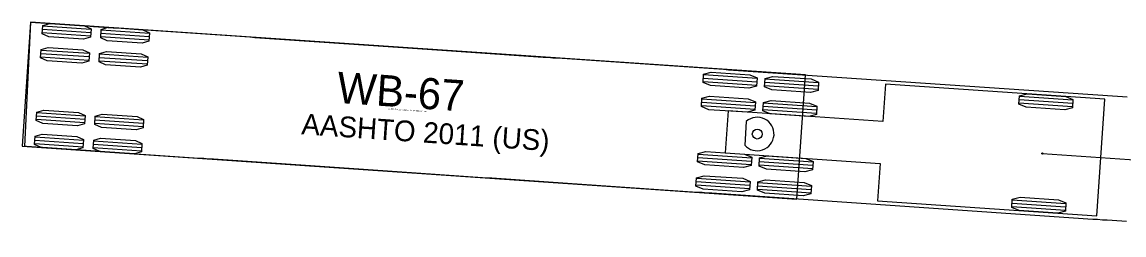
# Model space of a CAD drawing. Extents: x 2175591 to 2194071, y 76570 to 86955.
# Drawn here: x 2192626.4 to 2192701.6, y 86940.2 to 86954.7 of the extents above; entities that cross this region are included whole.
import ezdxf

# ---------------------------------------------------------------- set-up
doc = ezdxf.new("R2010")
doc.units = 0
doc.layers.add('-NOPLT', color=7, linetype='Continuous')

msp = doc.modelspace()

# ---------------------------------------------------------------- linework, layer by layer
at = {"layer": '-NOPLT'}
for p, q in [((2192626.957, 86954.687), (2192626.379, 86946.206)), ((2192679.834, 86951.077), (2192626.957, 86954.687)), ((2192631.067, 86953.947), (2192627.774, 86954.172)), ((2192631.082, 86954.175), (2192627.79, 86954.4)), ((2192635.073, 86953.903), (2192631.781, 86954.128)), ((2192631.051, 86953.718), (2192627.759, 86953.943)), ((2192635.042, 86953.446), (2192631.749, 86953.67)), ((2192635.057, 86953.674), (2192631.765, 86953.899)), ((2192630.97, 86952.529), (2192627.678, 86952.754)), ((2192630.939, 86952.072), (2192627.646, 86952.297)), ((2192630.954, 86952.301), (2192627.662, 86952.525)), ((2192634.929, 86951.8), (2192631.637, 86952.024)), ((2192634.945, 86952.028), (2192631.653, 86952.253)), ((2192634.961, 86952.257), (2192631.668, 86952.482)), ((2192676.543, 86950.822), (2192672.885, 86951.071)), ((2192679.256, 86942.597), (2192679.834, 86951.077)), ((2192679.834, 86951.077), (2192679.834, 86951.077)), ((2192676.511, 86950.364), (2192672.853, 86950.614)), ((2192676.527, 86950.593), (2192672.869, 86950.843)), ((2192680.702, 86950.078), (2192677.044, 86950.328)), ((2192680.717, 86950.307), (2192677.059, 86950.557)), ((2192680.733, 86950.535), (2192677.075, 86950.785)), ((2192685.305, 86950.453), (2192685.13, 86947.892)), ((2192700.27, 86949.432), (2192685.305, 86950.453)), ((2192698.093, 86949.35), (2192694.434, 86949.6)), ((2192676.399, 86948.718), (2192672.741, 86948.968)), ((2192676.415, 86948.947), (2192672.757, 86949.196)), ((2192676.43, 86949.175), (2192672.772, 86949.425)), ((2192680.605, 86948.661), (2192676.947, 86948.91)), ((2192680.621, 86948.889), (2192676.962, 86949.139)), ((2192698.061, 86948.893), (2192694.403, 86949.143)), ((2192698.077, 86949.122), (2192694.419, 86949.372)), ((2192699.725, 86941.45), (2192700.27, 86949.432)), ((2192700.27, 86949.432), (2192700.27, 86949.432)), ((2192630.663, 86948.027), (2192627.37, 86948.252)), ((2192630.678, 86948.256), (2192627.386, 86948.481)), ((2192634.669, 86947.983), (2192631.377, 86948.208)), ((2192674.554, 86948.614), (2192674.359, 86945.754)), ((2192685.13, 86947.892), (2192674.554, 86948.614)), ((2192680.589, 86948.432), (2192676.931, 86948.682)), ((2192630.647, 86947.799), (2192627.355, 86948.023)), ((2192634.638, 86947.526), (2192631.345, 86947.751)), ((2192634.653, 86947.755), (2192631.361, 86947.98)), ((2192675.801, 86947.903), (2192675.691, 86946.29)), ((2192630.55, 86946.381), (2192627.258, 86946.606)), ((2192630.566, 86946.61), (2192627.273, 86946.834)), ((2192634.556, 86946.337), (2192631.264, 86946.562)), ((2192626.379, 86946.206), (2192679.256, 86942.597)), ((2192630.535, 86946.152), (2192627.242, 86946.377)), ((2192634.525, 86945.88), (2192631.233, 86946.105)), ((2192634.541, 86946.109), (2192631.249, 86946.333)), ((2192676.141, 86944.944), (2192672.483, 86945.193)), ((2192676.157, 86945.172), (2192672.499, 86945.422)), ((2192676.173, 86945.401), (2192672.515, 86945.651)), ((2192674.359, 86945.754), (2192684.935, 86945.032)), ((2192680.347, 86944.886), (2192676.689, 86945.136)), ((2192680.363, 86945.115), (2192676.705, 86945.364)), ((2192684.935, 86945.032), (2192684.76, 86942.472)), ((2192696.007, 86945.713), (2192777.484, 86940.151)), ((2192680.332, 86944.658), (2192676.674, 86944.907)), ((2192676.029, 86943.297), (2192672.371, 86943.547)), ((2192676.045, 86943.526), (2192672.387, 86943.776)), ((2192676.06, 86943.755), (2192672.402, 86944.004)), ((2192680.251, 86943.469), (2192676.592, 86943.718)), ((2192680.219, 86943.011), (2192676.561, 86943.261)), ((2192680.235, 86943.24), (2192676.577, 86943.49)), ((2192684.76, 86942.472), (2192699.725, 86941.45)), ((2192697.579, 86941.826), (2192693.921, 86942.076)), ((2192697.595, 86942.055), (2192693.936, 86942.305)), ((2192697.61, 86942.284), (2192693.952, 86942.533))]:
    msp.add_line(p, q, dxfattribs=at)
for points in [[(2192701.753, 86941.061), (2192701.424, 86941.084), (2192701.094, 86941.106), (2192700.765, 86941.129), (2192700.436, 86941.151), (2192700.107, 86941.173), (2192699.778, 86941.196), (2192699.448, 86941.218), (2192699.119, 86941.241), (2192698.79, 86941.263), (2192698.461, 86941.286), (2192698.131, 86941.308), (2192697.802, 86941.331), (2192697.473, 86941.353), (2192697.144, 86941.376), (2192696.815, 86941.398), (2192696.485, 86941.421), (2192696.156, 86941.443), (2192695.827, 86941.466), (2192695.498, 86941.488), (2192695.168, 86941.511), (2192694.839, 86941.533), (2192694.51, 86941.556), (2192694.181, 86941.578), (2192693.852, 86941.6), (2192693.522, 86941.623), (2192693.193, 86941.645), (2192692.864, 86941.668), (2192692.535, 86941.69), (2192692.206, 86941.713), (2192691.876, 86941.735), (2192691.547, 86941.758), (2192691.218, 86941.78), (2192690.889, 86941.803), (2192690.559, 86941.825), (2192690.23, 86941.848), (2192689.901, 86941.87), (2192689.572, 86941.893), (2192689.243, 86941.915), (2192688.913, 86941.938), (2192688.584, 86941.96), (2192688.255, 86941.983), (2192687.926, 86942.005), (2192687.596, 86942.027), (2192687.267, 86942.05), (2192686.938, 86942.072), (2192686.609, 86942.095), (2192686.28, 86942.117), (2192685.95, 86942.14), (2192685.621, 86942.162), (2192685.292, 86942.185), (2192684.963, 86942.207), (2192684.633, 86942.23), (2192684.304, 86942.252), (2192683.975, 86942.275), (2192683.646, 86942.297), (2192683.317, 86942.32), (2192682.987, 86942.342), (2192682.658, 86942.365), (2192682.329, 86942.387), (2192682, 86942.41), (2192681.671, 86942.432), (2192681.341, 86942.454), (2192681.012, 86942.477), (2192680.683, 86942.499), (2192680.354, 86942.522), (2192680.024, 86942.544), (2192679.695, 86942.567), (2192679.366, 86942.589), (2192679.037, 86942.612), (2192678.708, 86942.634), (2192678.378, 86942.657), (2192678.049, 86942.679), (2192677.72, 86942.702), (2192677.391, 86942.724), (2192677.061, 86942.747), (2192676.732, 86942.769), (2192676.403, 86942.792), (2192676.074, 86942.814), (2192675.745, 86942.837), (2192675.415, 86942.859), (2192675.086, 86942.881), (2192674.757, 86942.904), (2192674.428, 86942.926), (2192674.099, 86942.949), (2192673.769, 86942.971), (2192673.44, 86942.994), (2192673.111, 86943.016), (2192672.782, 86943.039), (2192672.452, 86943.061), (2192672.123, 86943.084), (2192671.794, 86943.106), (2192671.465, 86943.129), (2192671.136, 86943.151), (2192670.807, 86943.174), (2192670.478, 86943.196), (2192670.149, 86943.219), (2192669.82, 86943.241), (2192669.491, 86943.263), (2192669.162, 86943.286), (2192668.834, 86943.308), (2192668.505, 86943.331), (2192668.177, 86943.353), (2192667.849, 86943.375), (2192667.521, 86943.398), (2192667.193, 86943.42), (2192666.866, 86943.443), (2192666.538, 86943.465), (2192666.211, 86943.487), (2192665.885, 86943.51), (2192665.558, 86943.532), (2192665.232, 86943.554), (2192664.906, 86943.576), (2192664.581, 86943.599), (2192664.255, 86943.621), (2192663.93, 86943.643), (2192663.605, 86943.665), (2192663.281, 86943.687), (2192662.957, 86943.709), (2192662.633, 86943.732), (2192662.309, 86943.754), (2192661.986, 86943.776), (2192661.663, 86943.798), (2192661.34, 86943.82), (2192661.017, 86943.842), (2192660.695, 86943.864), (2192660.372, 86943.886), (2192660.05, 86943.908), (2192659.727, 86943.93), (2192659.405, 86943.952), (2192659.083, 86943.974), (2192658.761, 86943.996), (2192658.439, 86944.018), (2192658.117, 86944.04), (2192657.794, 86944.062), (2192657.472, 86944.084), (2192657.15, 86944.106), (2192656.828, 86944.128), (2192656.505, 86944.15), (2192656.183, 86944.172), (2192655.86, 86944.194), (2192655.537, 86944.216), (2192655.214, 86944.238), (2192654.891, 86944.26), (2192654.567, 86944.282), (2192654.243, 86944.304), (2192653.919, 86944.326), (2192653.595, 86944.349), (2192653.271, 86944.371), (2192652.946, 86944.393), (2192652.621, 86944.415), (2192652.296, 86944.437), (2192651.97, 86944.459), (2192651.644, 86944.482), (2192651.318, 86944.504), (2192650.991, 86944.526), (2192650.664, 86944.549), (2192650.337, 86944.571), (2192650.009, 86944.593), (2192649.681, 86944.616), (2192649.353, 86944.638), (2192649.024, 86944.661), (2192648.696, 86944.683), (2192648.367, 86944.705), (2192648.037, 86944.728), (2192647.708, 86944.75), (2192647.378, 86944.773), (2192647.048, 86944.795), (2192646.718, 86944.818), (2192646.388, 86944.841), (2192646.057, 86944.863), (2192645.727, 86944.886), (2192645.396, 86944.908), (2192645.065, 86944.931), (2192644.735, 86944.953), (2192644.404, 86944.976), (2192644.073, 86944.999), (2192643.742, 86945.021), (2192643.411, 86945.044), (2192643.08, 86945.066), (2192642.75, 86945.089), (2192642.419, 86945.111), (2192642.088, 86945.134), (2192641.757, 86945.157), (2192641.426, 86945.179), (2192641.095, 86945.202), (2192640.765, 86945.224), (2192640.434, 86945.247), (2192640.103, 86945.27), (2192639.772, 86945.292), (2192639.442, 86945.315), (2192639.111, 86945.337), (2192638.781, 86945.36), (2192638.45, 86945.382), (2192638.12, 86945.405), (2192637.789, 86945.427), (2192637.459, 86945.45), (2192637.128, 86945.473), (2192636.798, 86945.495), (2192636.468, 86945.518), (2192636.137, 86945.54), (2192635.807, 86945.563), (2192635.477, 86945.585), (2192635.147, 86945.608), (2192634.817, 86945.63), (2192634.486, 86945.653), (2192634.156, 86945.675), (2192633.826, 86945.698), (2192633.496, 86945.721), (2192633.166, 86945.743), (2192632.836, 86945.766), (2192632.507, 86945.788), (2192632.177, 86945.811), (2192631.847, 86945.833), (2192631.737, 86945.841), (2192631.627, 86945.848), (2192631.517, 86945.856), (2192631.407, 86945.863), (2192631.297, 86945.871), (2192631.187, 86945.878), (2192631.077, 86945.886), (2192630.967, 86945.893), (2192630.858, 86945.901), (2192630.748, 86945.908), (2192630.638, 86945.916), (2192630.528, 86945.923), (2192630.418, 86945.931), (2192630.308, 86945.938), (2192630.198, 86945.946), (2192630.088, 86945.953), (2192629.978, 86945.961), (2192629.869, 86945.968), (2192629.759, 86945.976), (2192629.649, 86945.983), (2192629.539, 86945.991), (2192629.429, 86945.998), (2192629.319, 86946.006), (2192629.209, 86946.013), (2192629.1, 86946.021), (2192628.99, 86946.028), (2192628.88, 86946.036), (2192628.77, 86946.043), (2192628.66, 86946.051), (2192628.55, 86946.058), (2192628.441, 86946.066), (2192628.331, 86946.073), (2192628.221, 86946.081), (2192628.111, 86946.088), (2192628.001, 86946.096), (2192627.891, 86946.103), (2192627.782, 86946.111), (2192627.672, 86946.118), (2192627.562, 86946.126), (2192627.452, 86946.133), (2192627.343, 86946.141), (2192627.233, 86946.148), (2192627.123, 86946.156), (2192627.013, 86946.163), (2192626.903, 86946.171), (2192626.794, 86946.178), (2192626.684, 86946.186), (2192626.574, 86946.193), (2192626.985, 86954.685)], [(2192626.985, 86954.685), (2192627.03, 86954.682), (2192627.075, 86954.679), (2192627.119, 86954.676), (2192627.163, 86954.673), (2192627.206, 86954.67), (2192627.25, 86954.667), (2192627.292, 86954.664), (2192627.447, 86954.653), (2192627.559, 86954.646), (2192627.671, 86954.638), (2192627.783, 86954.63), (2192627.895, 86954.623), (2192628.007, 86954.615), (2192628.119, 86954.607), (2192628.231, 86954.6), (2192628.343, 86954.592), (2192628.455, 86954.584), (2192628.567, 86954.577), (2192628.679, 86954.569), (2192628.791, 86954.562), (2192628.903, 86954.554), (2192629.015, 86954.546), (2192629.127, 86954.539), (2192629.239, 86954.531), (2192629.351, 86954.523), (2192629.463, 86954.516), (2192629.575, 86954.508), (2192629.687, 86954.5), (2192629.8, 86954.493), (2192629.912, 86954.485), (2192630.024, 86954.477), (2192630.136, 86954.47), (2192630.248, 86954.462), (2192630.36, 86954.454), (2192630.472, 86954.447), (2192630.584, 86954.439), (2192630.696, 86954.431), (2192630.808, 86954.424), (2192630.92, 86954.416), (2192631.033, 86954.409), (2192631.145, 86954.401), (2192631.257, 86954.393), (2192631.369, 86954.386), (2192631.481, 86954.378), (2192631.593, 86954.37), (2192631.705, 86954.363), (2192631.817, 86954.355), (2192631.93, 86954.347), (2192632.042, 86954.34), (2192632.154, 86954.332), (2192632.266, 86954.324), (2192632.378, 86954.317), (2192632.49, 86954.309), (2192632.602, 86954.301), (2192632.715, 86954.294), (2192632.827, 86954.286), (2192633.163, 86954.263), (2192633.5, 86954.24), (2192633.836, 86954.217), (2192634.173, 86954.194), (2192634.51, 86954.171), (2192634.846, 86954.148), (2192635.183, 86954.125), (2192635.52, 86954.102), (2192635.857, 86954.079), (2192636.194, 86954.056), (2192636.531, 86954.033), (2192636.867, 86954.01), (2192637.204, 86953.987), (2192637.541, 86953.964), (2192637.878, 86953.941), (2192638.215, 86953.918), (2192638.553, 86953.895), (2192638.89, 86953.872), (2192639.227, 86953.849), (2192639.564, 86953.826), (2192639.901, 86953.803), (2192640.239, 86953.78), (2192640.576, 86953.757), (2192640.913, 86953.734), (2192641.251, 86953.711), (2192641.588, 86953.688), (2192641.925, 86953.665), (2192642.263, 86953.642), (2192642.6, 86953.619), (2192642.938, 86953.596), (2192643.276, 86953.573), (2192643.613, 86953.55), (2192643.951, 86953.527), (2192644.288, 86953.504), (2192644.626, 86953.481), (2192644.963, 86953.458), (2192645.301, 86953.434), (2192645.639, 86953.411), (2192645.976, 86953.388), (2192646.314, 86953.365), (2192646.651, 86953.342), (2192646.988, 86953.319), (2192647.326, 86953.296), (2192647.663, 86953.273), (2192648, 86953.25), (2192648.336, 86953.227), (2192648.673, 86953.204), (2192649.01, 86953.181), (2192649.346, 86953.158), (2192649.682, 86953.135), (2192650.017, 86953.113), (2192650.353, 86953.09), (2192650.688, 86953.067), (2192651.023, 86953.044), (2192651.358, 86953.021), (2192651.692, 86952.998), (2192652.026, 86952.975), (2192652.359, 86952.953), (2192652.693, 86952.93), (2192653.026, 86952.907), (2192653.358, 86952.884), (2192653.691, 86952.862), (2192654.022, 86952.839), (2192654.354, 86952.816), (2192654.685, 86952.794), (2192655.017, 86952.771), (2192655.347, 86952.749), (2192655.678, 86952.726), (2192656.008, 86952.704), (2192656.338, 86952.681), (2192656.668, 86952.659), (2192656.998, 86952.636), (2192657.327, 86952.614), (2192657.656, 86952.591), (2192657.985, 86952.569), (2192658.314, 86952.546), (2192658.643, 86952.524), (2192658.972, 86952.501), (2192659.301, 86952.479), (2192659.63, 86952.456), (2192659.958, 86952.434), (2192660.287, 86952.411), (2192660.616, 86952.389), (2192660.944, 86952.367), (2192661.273, 86952.344), (2192661.602, 86952.322), (2192661.931, 86952.299), (2192662.26, 86952.277), (2192662.589, 86952.254), (2192662.918, 86952.232), (2192663.248, 86952.209), (2192663.578, 86952.187), (2192663.907, 86952.164), (2192664.238, 86952.142), (2192664.568, 86952.119), (2192664.899, 86952.097), (2192665.23, 86952.074), (2192665.561, 86952.051), (2192665.893, 86952.029), (2192666.225, 86952.006), (2192666.557, 86951.983), (2192666.89, 86951.961), (2192667.222, 86951.938), (2192667.555, 86951.915), (2192667.889, 86951.893), (2192668.222, 86951.87), (2192668.556, 86951.847), (2192668.891, 86951.824), (2192669.225, 86951.801), (2192669.56, 86951.779), (2192669.894, 86951.756), (2192670.229, 86951.733), (2192670.564, 86951.71), (2192670.9, 86951.687), (2192671.235, 86951.664), (2192671.571, 86951.641), (2192671.906, 86951.618), (2192672.242, 86951.595), (2192672.577, 86951.572), (2192672.913, 86951.55), (2192673.249, 86951.527), (2192673.585, 86951.504), (2192673.921, 86951.481), (2192674.256, 86951.458), (2192674.592, 86951.435), (2192674.928, 86951.412), (2192675.264, 86951.389), (2192675.6, 86951.366), (2192675.936, 86951.343), (2192676.272, 86951.32), (2192676.608, 86951.297), (2192676.944, 86951.274), (2192677.28, 86951.252), (2192677.615, 86951.229), (2192677.951, 86951.206), (2192678.287, 86951.183), (2192678.623, 86951.16), (2192678.959, 86951.137), (2192679.295, 86951.114), (2192679.631, 86951.091), (2192679.967, 86951.068), (2192680.303, 86951.045), (2192680.639, 86951.022), (2192680.974, 86950.999), (2192681.31, 86950.976), (2192681.646, 86950.953), (2192681.982, 86950.93), (2192682.318, 86950.908), (2192682.654, 86950.885), (2192682.99, 86950.862), (2192683.326, 86950.839), (2192683.662, 86950.816), (2192683.998, 86950.793), (2192684.333, 86950.77), (2192684.669, 86950.747), (2192685.005, 86950.724), (2192685.341, 86950.701), (2192685.677, 86950.678), (2192686.013, 86950.655), (2192686.349, 86950.632), (2192686.685, 86950.609), (2192687.021, 86950.587), (2192687.357, 86950.564), (2192687.692, 86950.541), (2192688.028, 86950.518), (2192688.364, 86950.495), (2192688.7, 86950.472), (2192689.036, 86950.449), (2192689.372, 86950.426), (2192689.708, 86950.403), (2192690.044, 86950.38), (2192690.38, 86950.357), (2192690.716, 86950.334), (2192691.051, 86950.311), (2192691.387, 86950.288), (2192691.723, 86950.266), (2192692.059, 86950.243), (2192692.395, 86950.22), (2192692.731, 86950.197), (2192693.067, 86950.174), (2192693.403, 86950.151), (2192693.739, 86950.128), (2192694.075, 86950.105), (2192694.41, 86950.082), (2192694.746, 86950.059), (2192695.082, 86950.036), (2192695.418, 86950.013), (2192695.754, 86949.99), (2192696.09, 86949.967), (2192696.426, 86949.945), (2192696.762, 86949.922), (2192697.098, 86949.899), (2192697.434, 86949.876), (2192697.769, 86949.853), (2192698.105, 86949.83), (2192698.441, 86949.807), (2192698.777, 86949.784), (2192699.113, 86949.761), (2192699.449, 86949.738), (2192699.785, 86949.715), (2192700.121, 86949.692), (2192700.457, 86949.669), (2192700.793, 86949.646), (2192701.128, 86949.623), (2192701.464, 86949.601), (2192701.8, 86949.578)]]:
    msp.add_lwpolyline(points, dxfattribs=at)
for points in [[(2192631.086, 86954.232), (2192631.047, 86953.661), (2192630.574, 86953.521), (2192628.204, 86953.683), (2192627.755, 86953.886), (2192627.794, 86954.457), (2192628.266, 86954.597), (2192630.637, 86954.436)], [(2192635.077, 86953.96), (2192635.038, 86953.389), (2192634.565, 86953.249), (2192632.195, 86953.41), (2192631.746, 86953.614), (2192631.784, 86954.184), (2192632.257, 86954.325), (2192634.628, 86954.163)], [(2192630.974, 86952.586), (2192630.935, 86952.015), (2192630.462, 86951.875), (2192628.092, 86952.037), (2192627.642, 86952.24), (2192627.681, 86952.811), (2192628.154, 86952.951), (2192630.525, 86952.789)], [(2192634.964, 86952.314), (2192634.925, 86951.743), (2192634.453, 86951.602), (2192632.082, 86951.764), (2192631.633, 86951.968), (2192631.672, 86952.538), (2192632.145, 86952.679), (2192634.515, 86952.517)], [(2192676.547, 86950.878), (2192676.508, 86950.308), (2192675.984, 86950.171), (2192673.35, 86950.35), (2192672.849, 86950.557), (2192672.888, 86951.128), (2192673.412, 86951.265), (2192676.046, 86951.085)], [(2192680.737, 86950.592), (2192680.698, 86950.022), (2192680.174, 86949.885), (2192677.54, 86950.064), (2192677.04, 86950.271), (2192677.079, 86950.842), (2192677.603, 86950.979), (2192680.236, 86950.799)], [(2192676.434, 86949.232), (2192676.395, 86948.661), (2192675.871, 86948.524), (2192673.237, 86948.704), (2192672.737, 86948.911), (2192672.776, 86949.482), (2192673.3, 86949.619), (2192675.934, 86949.439)], [(2192698.096, 86949.407), (2192698.057, 86948.836), (2192697.534, 86948.7), (2192694.9, 86948.879), (2192694.399, 86949.086), (2192694.438, 86949.657), (2192694.962, 86949.794), (2192697.596, 86949.614)], [(2192680.624, 86948.946), (2192680.585, 86948.375), (2192680.062, 86948.238), (2192677.428, 86948.418), (2192676.927, 86948.625), (2192676.966, 86949.196), (2192677.49, 86949.333), (2192680.124, 86949.153)], [(2192630.682, 86948.313), (2192630.643, 86947.742), (2192630.17, 86947.601), (2192627.8, 86947.763), (2192627.351, 86947.967), (2192627.39, 86948.537), (2192627.862, 86948.678), (2192630.233, 86948.516)], [(2192634.673, 86948.04), (2192634.634, 86947.469), (2192634.161, 86947.329), (2192631.791, 86947.491), (2192631.341, 86947.694), (2192631.38, 86948.265), (2192631.853, 86948.405), (2192634.224, 86948.244)], [(2192630.57, 86946.666), (2192630.531, 86946.096), (2192630.058, 86945.955), (2192627.688, 86946.117), (2192627.238, 86946.32), (2192627.277, 86946.891), (2192627.75, 86947.032), (2192630.12, 86946.87)], [(2192634.56, 86946.394), (2192634.521, 86945.823), (2192634.049, 86945.683), (2192631.678, 86945.845), (2192631.229, 86946.048), (2192631.268, 86946.619), (2192631.741, 86946.759), (2192634.111, 86946.597)], [(2192676.177, 86945.458), (2192676.138, 86944.887), (2192675.614, 86944.75), (2192672.98, 86944.93), (2192672.479, 86945.137), (2192672.518, 86945.707), (2192673.042, 86945.844), (2192675.676, 86945.664)], [(2192680.367, 86945.171), (2192680.328, 86944.601), (2192679.804, 86944.464), (2192677.17, 86944.644), (2192676.67, 86944.851), (2192676.709, 86945.421), (2192677.233, 86945.558), (2192679.866, 86945.378)], [(2192676.064, 86943.811), (2192676.025, 86943.241), (2192675.501, 86943.104), (2192672.867, 86943.283), (2192672.367, 86943.49), (2192672.406, 86944.061), (2192672.93, 86944.198), (2192675.564, 86944.018)], [(2192680.254, 86943.525), (2192680.215, 86942.955), (2192679.692, 86942.818), (2192677.058, 86942.997), (2192676.557, 86943.204), (2192676.596, 86943.775), (2192677.12, 86943.912), (2192679.754, 86943.732)], [(2192697.614, 86942.34), (2192697.575, 86941.77), (2192697.051, 86941.633), (2192694.417, 86941.812), (2192693.917, 86942.019), (2192693.956, 86942.59), (2192694.48, 86942.727), (2192697.114, 86942.547)]]:
    msp.add_lwpolyline(points, close=True, dxfattribs=at)
for centre, radius in [((2192676.552, 86947.041), 0.34), ((2192696.007, 86945.713), 0.0417)]:
    msp.add_circle(centre, radius, dxfattribs=at)
msp.add_arc((2192676.552, 86947.041), 1.143, 221.09483, 131.09483, dxfattribs=at)

# ---------------------------------------------------------------- texts
for s, height, p in [('WB-67', 2.125, (2192647.818, 86949.173)), ('(c) 2022 Transoft Solutions, Inc. All rights reserved.', 0.085, (2192651.367, 86948.718)), ('AASHTO 2011 (US)', 1.41667, (2192645.415, 86947.03))]:
    msp.add_text(s, height=height, rotation=356.09483, dxfattribs=at).set_placement(p)

doc.saveas('drawing.dxf')
